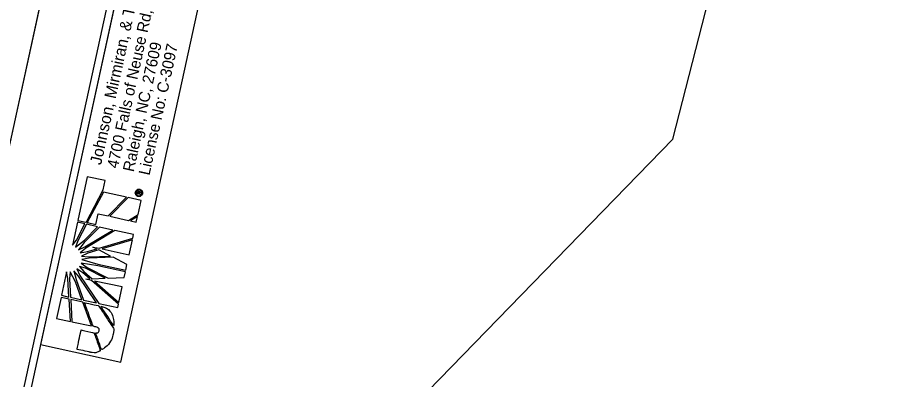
# Model space of a CAD drawing. Extents: x 1616330 to 1616903, y 901240 to 902105.
# Drawn here: x 1616448.1 to 1616566.5, y 901839.4 to 901889.1 of the extents above; entities that cross this region are included whole.
import ezdxf

# ---------------------------------------------------------------- set-up
doc = ezdxf.new("R2010")
doc.units = 0
for name, color, linetype in [('Default', 7, 'Continuous'), ('Sheet Border Standard 30in CELL', 7, 'Continuous'), ('Sheet Clip Boundary CELL', 7, 'Continuous'), ('Sheet Cutting Line CELL', 7, 'Continuous'), ('Sheet Plot Border Inside CELL', 7, 'Continuous'), ('Sheet Plot Border Outside CELL', 7, 'Continuous')]:
    doc.layers.add(name, color=color, linetype=linetype)

msp = doc.modelspace()

# ---------------------------------------------------------------- linework, layer by layer
at = {"layer": 'Default'}
for p, q in [((1616457.71, 901867.25), (1616456.4, 901861.24)), ((1616460.17, 901866.71), (1616457.71, 901867.25)), ((1616459.89, 901865.43), (1616460.17, 901866.71)), ((1616457.54, 901860.99), (1616459.89, 901865.43)), ((1616459.94, 901865.11), (1616457.71, 901860.95)), ((1616463.09, 901864.42), (1616459.94, 901865.11)), ((1616464.32, 901865.13), (1616464.42, 901865.11)), ((1616464.42, 901865.11), (1616464.32, 901865.13)), ((1616464.54, 901864.9), (1616464.58, 901865.08)), ((1616464.58, 901865.08), (1616464.59, 901865.1)), ((1616464.58, 901865.08), (1616464.67, 901865.06)), ((1616464.67, 901865.06), (1616464.58, 901865.08)), ((1616464.67, 901865.06), (1616464.65, 901864.98)), ((1616464.67, 901865.07), (1616464.67, 901865.06)), ((1616464.75, 901864.96), (1616464.77, 901865.03)), ((1616464.77, 901865.03), (1616464.77, 901865.04)), ((1616464.77, 901865.03), (1616464.85, 901865.02)), ((1616464.85, 901865.02), (1616464.77, 901865.03)), ((1616464.85, 901865.02), (1616464.83, 901864.94)), ((1616464.85, 901865.02), (1616464.85, 901865.02)), ((1616460.57, 901861.87), (1616463.09, 901864.42)), ((1616463.31, 901864.38), (1616460.81, 901861.82)), ((1616465.09, 901863.99), (1616463.31, 901864.38)), ((1616464.98, 901864.8), (1616464.54, 901864.9)), ((1616464.65, 901864.98), (1616464.75, 901864.96)), ((1616464.67, 901862.05), (1616465.09, 901863.99)), ((1616464.83, 901864.94), (1616465, 901864.9)), ((1616465, 901864.9), (1616464.98, 901864.8)), ((1616465.19, 901864.94), (1616465.19, 901864.95)), ((1616465.19, 901864.94), (1616465.29, 901864.92)), ((1616465.29, 901864.92), (1616465.19, 901864.94)), ((1616465.29, 901864.93), (1616465.29, 901864.92)), ((1616458.88, 901860.7), (1616459.2, 901862.17)), ((1616459.2, 901862.17), (1616460.57, 901861.87)), ((1616460.81, 901861.82), (1616463.36, 901861.26)), ((1616463.36, 901861.26), (1616464.67, 901862.05)), ((1616464.6, 901861.77), (1616463.64, 901861.2)), ((1616464.44, 901861.03), (1616464.6, 901861.77)), ((1616456.37, 901861.01), (1616455.67, 901857.85)), ((1616456.22, 901858.57), (1616457.4, 901860.79)), ((1616457.4, 901860.79), (1616456.37, 901861.01)), ((1616456.4, 901861.24), (1616457.51, 901861)), ((1616457.61, 901860.74), (1616456.41, 901858.44)), ((1616459.38, 901860.34), (1616457.28, 901858.22)), ((1616457.34, 901858.57), (1616459.12, 901860.39)), ((1616457.51, 901861), (1616457.54, 901860.99)), ((1616459.12, 901860.39), (1616457.61, 901860.74)), ((1616457.71, 901860.95), (1616457.73, 901860.95)), ((1616457.73, 901860.95), (1616458.88, 901860.7)), ((1616461.21, 901859.94), (1616459.38, 901860.34)), ((1616463.64, 901861.2), (1616464.44, 901861.03)), ((1616457.4, 901857.62), (1616461.21, 901859.94)), ((1616461.51, 901859.88), (1616457.51, 901857.46)), ((1616464.07, 901859.32), (1616461.51, 901859.88)), ((1616463.96, 901858.81), (1616464.07, 901859.32)), ((1616455.67, 901857.85), (1616456.22, 901858.57)), ((1616456.1, 901857.58), (1616457.34, 901858.57)), ((1616456.41, 901858.44), (1616456.1, 901857.58)), ((1616457.28, 901858.22), (1616456.49, 901857.24)), ((1616459.33, 901857.43), (1616463.96, 901858.81)), ((1616463.9, 901858.58), (1616459.74, 901857.34)), ((1616463.45, 901856.53), (1616463.9, 901858.58)), ((1616456.49, 901857.24), (1616457.4, 901857.62)), ((1616457.51, 901857.46), (1616456.76, 901856.83)), ((1616456.76, 901856.83), (1616457.75, 901856.98)), ((1616457.78, 901856.76), (1616456.93, 901856.37)), ((1616457.75, 901856.98), (1616459.02, 901857.34)), ((1616459.28, 901857.21), (1616457.78, 901856.76)), ((1616459.02, 901857.34), (1616458.49, 901857.61)), ((1616458.49, 901857.61), (1616459.33, 901857.43)), ((1616460.91, 901856.37), (1616459.28, 901857.21)), ((1616459.74, 901857.34), (1616463.45, 901856.53)), ((1616456.93, 901856.37), (1616457.87, 901856.26)), ((1616457.96, 901856.06), (1616456.96, 901855.88)), ((1616456.96, 901855.88), (1616459.18, 901855.24)), ((1616457.87, 901856.26), (1616460.91, 901856.37)), ((1616461.27, 901856.2), (1616457.96, 901856.06)), ((1616463.16, 901855.21), (1616461.27, 901856.2)), ((1616456.28, 901854.61), (1616456.7, 901853.72)), ((1616457.12, 901854.06), (1616456.28, 901854.61)), ((1616456.63, 901854.96), (1616457.23, 901854.24)), ((1616457.49, 901854.69), (1616456.63, 901854.96)), ((1616459.14, 901855.04), (1616456.86, 901855.41)), ((1616456.86, 901855.41), (1616457.69, 901854.82)), ((1616460.18, 901853.33), (1616457.49, 901854.69)), ((1616457.69, 901854.82), (1616460.6, 901853.34)), ((1616462.95, 901854.21), (1616459.14, 901855.04)), ((1616459.18, 901855.24), (1616462.99, 901854.42)), ((1616462.99, 901854.42), (1616463.16, 901855.21)), ((1616454.87, 901854.2), (1616454.18, 901850.99)), ((1616455.06, 901853.3), (1616454.87, 901854.2)), ((1616455.2, 901850.76), (1616455.06, 901853.3)), ((1616455.37, 901854.21), (1616455.28, 901853.26)), ((1616455.28, 901853.26), (1616455.42, 901850.72)), ((1616456.08, 901852.82), (1616455.37, 901854.21)), ((1616456.52, 901853.63), (1616455.87, 901854.35)), ((1616455.87, 901854.35), (1616456.18, 901853.14)), ((1616459, 901849.94), (1616456.52, 901853.63)), ((1616456.7, 901853.72), (1616459.3, 901849.87)), ((1616458.08, 901853.23), (1616457.12, 901854.06)), ((1616457.23, 901854.24), (1616458.37, 901853.25)), ((1616457.53, 901853.2), (1616458.08, 901853.23)), ((1616458.29, 901853.03), (1616457.53, 901853.2)), ((1616458.37, 901853.25), (1616460.18, 901853.33)), ((1616460.6, 901853.34), (1616462.78, 901853.43)), ((1616462.78, 901853.43), (1616462.95, 901854.21)), ((1616456.97, 901850.38), (1616456.08, 901852.82)), ((1616456.18, 901853.14), (1616457.22, 901850.33)), ((1616462, 901849.78), (1616458.29, 901853.03)), ((1616462.51, 901852.14), (1616458.7, 901852.94)), ((1616458.7, 901852.94), (1616462.05, 901850)), ((1616462.05, 901850), (1616462.51, 901852.14)), ((1616454.18, 901850.99), (1616455.2, 901850.76)), ((1616454.13, 901850.69), (1616453.5, 901847.83)), ((1616455.23, 901850.45), (1616454.13, 901850.69)), ((1616455.4, 901847.42), (1616455.23, 901850.45)), ((1616455.42, 901850.72), (1616456.97, 901850.38)), ((1616457.09, 901850.04), (1616455.44, 901850.4)), ((1616455.44, 901850.4), (1616455.62, 901847.37)), ((1616458.28, 901846.79), (1616457.09, 901850.04)), ((1616457.22, 901850.33), (1616459, 901849.94)), ((1616459.3, 901849.87), (1616461.9, 901849.31)), ((1616461.9, 901849.31), (1616462, 901849.78)), ((1616453.5, 901847.83), (1616455.4, 901847.42)), ((1616455.62, 901847.37), (1616458.28, 901846.79))]:
    msp.add_line(p, q, dxfattribs=at)
msp.add_lwpolyline([(1616462.33, 901841.85), (1616475.65, 901902.93), (1616464.63, 901905.33), (1616451.31, 901844.26)], close=True, dxfattribs=at)
for points in [[(1616457.71, 901867.25), (1616456.4, 901861.24), (1616457.51, 901861), (1616457.54, 901860.99), (1616459.89, 901865.43), (1616460.17, 901866.71), (1616457.71, 901867.25)], [(1616457.71, 901860.95), (1616457.73, 901860.95), (1616458.88, 901860.7), (1616459.2, 901862.17), (1616460.57, 901861.87), (1616463.09, 901864.42), (1616459.94, 901865.11), (1616457.71, 901860.95)], [(1616464.96, 901865.19), (1616464.98, 901865.19), (1616465, 901865.19), (1616465.01, 901865.19), (1616465.06, 901865.19), (1616465.04, 901865.1)], [(1616460.81, 901861.82), (1616463.36, 901861.26), (1616464.67, 901862.05), (1616465.09, 901863.99), (1616463.31, 901864.38), (1616460.81, 901861.82), (1616460.81, 901861.82)], [(1616464.44, 901861.03), (1616464.44, 901861.03), (1616464.6, 901861.77), (1616463.64, 901861.2), (1616464.44, 901861.03)], [(1616456.22, 901858.57), (1616457.4, 901860.79), (1616456.37, 901861.01), (1616455.67, 901857.85), (1616456.22, 901858.57)], [(1616456.1, 901857.58), (1616457.34, 901858.57), (1616459.12, 901860.39), (1616457.61, 901860.74), (1616456.41, 901858.44), (1616456.1, 901857.58)], [(1616456.49, 901857.24), (1616457.4, 901857.62), (1616461.21, 901859.94), (1616459.38, 901860.34), (1616457.28, 901858.22), (1616456.49, 901857.24)], [(1616456.76, 901856.83), (1616457.75, 901856.98), (1616459.02, 901857.34), (1616458.49, 901857.61), (1616459.33, 901857.43), (1616463.96, 901858.81), (1616464.07, 901859.32), (1616461.51, 901859.88), (1616457.51, 901857.46), (1616456.76, 901856.83)], [(1616463.45, 901856.53), (1616463.9, 901858.58), (1616459.74, 901857.34), (1616463.45, 901856.53)], [(1616456.93, 901856.37), (1616457.87, 901856.26), (1616460.91, 901856.37), (1616459.28, 901857.21), (1616457.78, 901856.76), (1616456.93, 901856.37)], [(1616456.96, 901855.88), (1616459.18, 901855.24), (1616462.99, 901854.42), (1616463.16, 901855.21), (1616461.27, 901856.2), (1616457.96, 901856.06), (1616456.96, 901855.88)], [(1616456.28, 901854.61), (1616456.7, 901853.72), (1616459.3, 901849.87), (1616461.9, 901849.31), (1616462, 901849.78), (1616458.29, 901853.03), (1616457.53, 901853.2), (1616458.08, 901853.23), (1616457.12, 901854.06), (1616456.28, 901854.61)], [(1616456.63, 901854.96), (1616457.23, 901854.24), (1616458.37, 901853.25), (1616460.18, 901853.33), (1616457.49, 901854.69), (1616456.63, 901854.96)], [(1616457.69, 901854.82), (1616460.6, 901853.34), (1616462.78, 901853.43), (1616462.95, 901854.21), (1616459.14, 901855.04), (1616456.86, 901855.41), (1616457.69, 901854.82)], [(1616455.06, 901853.3), (1616454.87, 901854.2), (1616454.18, 901850.99), (1616455.2, 901850.76), (1616455.06, 901853.3)], [(1616455.42, 901850.72), (1616456.97, 901850.38), (1616456.08, 901852.82), (1616455.37, 901854.21), (1616455.28, 901853.26), (1616455.42, 901850.72)], [(1616457.22, 901850.33), (1616459, 901849.94), (1616456.52, 901853.63), (1616455.87, 901854.35), (1616456.18, 901853.14), (1616457.22, 901850.33)], [(1616462.05, 901850), (1616462.51, 901852.14), (1616458.7, 901852.94), (1616462.05, 901850)], [(1616455.4, 901847.42), (1616455.23, 901850.45), (1616454.13, 901850.69), (1616453.5, 901847.83), (1616455.4, 901847.42)], [(1616458.28, 901846.79), (1616457.09, 901850.04), (1616455.44, 901850.4), (1616455.62, 901847.37), (1616458.28, 901846.79)]]:
    msp.add_lwpolyline(points, dxfattribs=at)
for points, degree in [([(1616465.29, 901864.92), (1616465.26, 901864.79), (1616465.18, 901864.69), (1616465.07, 901864.61), (1616464.96, 901864.54), (1616464.83, 901864.51), (1616464.7, 901864.54), (1616464.56, 901864.57), (1616464.46, 901864.64), (1616464.39, 901864.76), (1616464.32, 901864.87), (1616464.29, 901865), (1616464.32, 901865.13)], 3), ([(1616464.32, 901865.13), (1616464.35, 901865.27), (1616464.43, 901865.37), (1616464.54, 901865.45), (1616464.65, 901865.52), (1616464.77, 901865.55), (1616464.91, 901865.52)], 3), ([(1616464.42, 901865.11), (1616464.39, 901865), (1616464.41, 901864.9), (1616464.46, 901864.81), (1616464.52, 901864.72), (1616464.61, 901864.66), (1616464.72, 901864.64), (1616464.82, 901864.61), (1616464.93, 901864.63), (1616465.02, 901864.69), (1616465.11, 901864.75), (1616465.17, 901864.84), (1616465.19, 901864.94)], 3), ([(1616465.19, 901864.95), (1616465.21, 901865.05), (1616465.2, 901865.15), (1616465.14, 901865.25), (1616465.08, 901865.34), (1616464.99, 901865.4), (1616464.89, 901865.42), (1616464.78, 901865.44), (1616464.67, 901865.43), (1616464.58, 901865.37), (1616464.49, 901865.31), (1616464.44, 901865.22), (1616464.42, 901865.11)], 3), ([(1616464.59, 901865.1), (1616464.61, 901865.21), (1616464.67, 901865.26), (1616464.76, 901865.24), (1616464.8, 901865.23), (1616464.82, 901865.21), (1616464.84, 901865.17)], 3), ([(1616464.77, 901865.04), (1616464.78, 901865.1), (1616464.77, 901865.14), (1616464.73, 901865.15), (1616464.7, 901865.15), (1616464.68, 901865.13), (1616464.67, 901865.07)], 3), ([(1616464.84, 901865.17), (1616464.86, 901865.19), (1616464.9, 901865.2), (1616464.96, 901865.19)], 2), ([(1616464.88, 901865.09), (1616464.87, 901865.08), (1616464.86, 901865.06), (1616464.85, 901865.02)], 2), ([(1616465.04, 901865.1), (1616465.02, 901865.09), (1616464.99, 901865.09), (1616464.96, 901865.09), (1616464.92, 901865.1), (1616464.9, 901865.1), (1616464.88, 901865.09)], 3), ([(1616464.91, 901865.52), (1616465.04, 901865.49), (1616465.15, 901865.41), (1616465.22, 901865.3), (1616465.29, 901865.19), (1616465.32, 901865.06), (1616465.29, 901864.93)], 3), ([(1616459.35, 901846.13), (1616459.31, 901845.96), (1616459.19, 901845.83), (1616458.86, 901845.84), (1616458.86, 901845.84), (1616459.68, 901843.51), (1616459.68, 901843.51), (1616460.48, 901844), (1616461.1, 901844.92), (1616461.28, 901845.78), (1616461.33, 901846), (1616461.35, 901846.17), (1616461.35, 901846.42), (1616461.35, 901846.42), (1616459.25, 901849.57), (1616459.25, 901849.57), (1616459.25, 901849.57), (1616457.33, 901849.99), (1616457.33, 901849.99), (1616457.33, 901849.99), (1616458.52, 901846.74), (1616458.52, 901846.74), (1616459.25, 901846.58), (1616459.4, 901846.36), (1616459.35, 901846.13)], 3), ([(1616459.35, 901846.13), (1616459.31, 901845.96), (1616459.19, 901845.83), (1616458.86, 901845.84), (1616458.86, 901845.84), (1616459.68, 901843.51), (1616459.68, 901843.51), (1616460.48, 901844), (1616461.1, 901844.92), (1616461.28, 901845.78), (1616461.33, 901846), (1616461.35, 901846.17), (1616461.35, 901846.42), (1616461.35, 901846.42), (1616459.25, 901849.57), (1616459.25, 901849.57), (1616459.25, 901849.57), (1616457.33, 901849.99), (1616457.33, 901849.99), (1616457.33, 901849.99), (1616458.52, 901846.74), (1616458.52, 901846.74), (1616459.25, 901846.58), (1616459.4, 901846.36), (1616459.35, 901846.13)], 3), ([(1616459.56, 901849.51), (1616459.56, 901849.51), (1616461.37, 901846.78), (1616461.37, 901846.78), (1616461.34, 901847.93), (1616460.85, 901849.17), (1616459.56, 901849.51)], 3), ([(1616456.88, 901846.24), (1616456.88, 901846.24), (1616456.3, 901843.59), (1616456.3, 901843.59), (1616456.3, 901843.59), (1616457.96, 901843.23), (1616457.96, 901843.23), (1616457.96, 901843.23), (1616458.13, 901843.19), (1616458.13, 901843.19), (1616458.65, 901843.08), (1616459.1, 901843.16), (1616459.51, 901843.39), (1616459.51, 901843.39), (1616458.66, 901845.85), (1616458.63, 901845.86), (1616458.63, 901845.86), (1616456.88, 901846.24), (1616456.88, 901846.24)], 3)]:
    msp.add_open_spline(points, degree=degree, dxfattribs=at)
at = {"layer": 'Sheet Border Standard 30in CELL'}
msp.add_lwpolyline([(1616481.7, 901983.51), (1616353.74, 901397.31), (1616764.08, 901307.74), (1616892.04, 901893.94)], close=True, dxfattribs=at)
at = {"layer": 'Sheet Clip Boundary CELL'}
msp.add_lwpolyline([(1616418.32, 901636.55), (1616453.3, 901785.32), (1616537.99, 901872.41), (1616557.7, 901949.17), (1616874.13, 901878.62), (1616760.29, 901314.11), (1616376.33, 901414.34)], close=True, dxfattribs=at)
at = {"layer": 'Sheet Cutting Line CELL'}
msp.add_line((1616473.38, 901992.29), (1616329.72, 901334.18), dxfattribs=at)
at = {"layer": 'Sheet Plot Border Inside CELL'}
msp.add_lwpolyline([(1616481.77, 901988.61), (1616339.61, 901337.35), (1616751.94, 901247.34), (1616894.1, 901898.61)], close=True, dxfattribs=at)
at = {"layer": 'Sheet Plot Border Outside CELL'}
msp.add_lwpolyline([(1616473.38, 901992.29), (1616329.72, 901334.18), (1616759.6, 901240.35), (1616903.26, 901898.45)], close=True, dxfattribs=at)

# ---------------------------------------------------------------- texts
at = {"layer": 'Default'}
for s, height, p in [('Johnson, Mirmiran, & Thompson Inc.', 1.5972, (1616459.62, 901868.79)), ('4700 Falls of Neuse Rd, Suite 100, ', 1.5516, (1616461.91, 901868.29)), ('Raleigh, NC, 27609', 1.5516, (1616464.08, 901867.82)), ('License No: C-3097', 1.5516, (1616466.24, 901867.35))]:
    msp.add_text(s, height=height, rotation=77.6932, dxfattribs=at).set_placement(p)

doc.saveas('drawing.dxf')
